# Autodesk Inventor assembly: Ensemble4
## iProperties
Shininess: 21.0
Compacted: True
Length Units: 11269
Angle Units: 11279
Time Units: 11290
Mass Units: 11283
Length Display Precision: 3
Angle Display Precision: 2
Created: 2001-12
Part Number: Ensemble4
Document SubType Name: Assemblage
Designer: pichon
Density: 0.0
Volumn: 0.0
Area: 0.0
PropertySet Name: Model Information
Control State: 0
Master: False
Checked Out: False
Author: pichon
